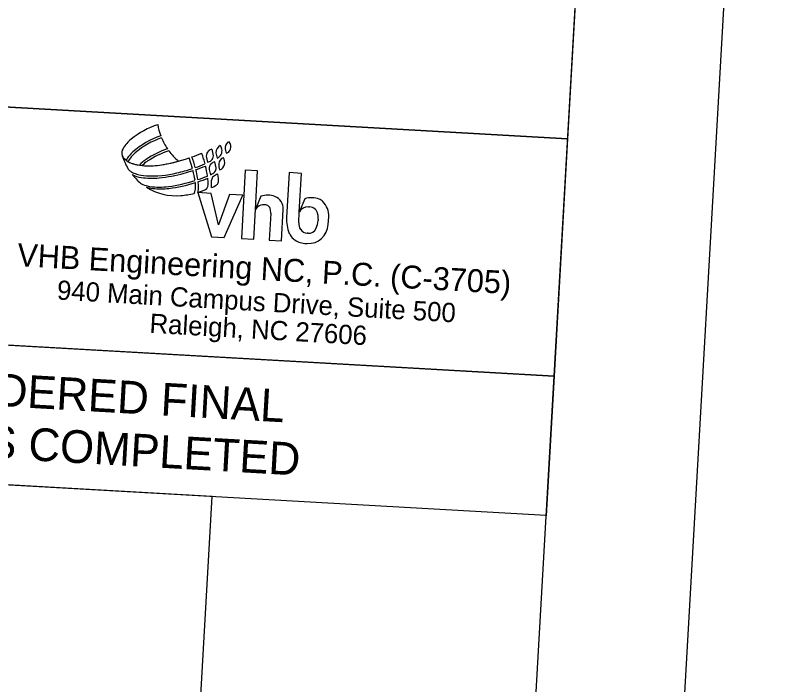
# Model space of a CAD drawing. Extents: x 2602909 to 2604669, y 617940 to 619640.
# Drawn here: x 2604541.7 to 2604668.9, y 618785.4 to 618898.1 of the extents above; entities that cross this region are included whole.
import ezdxf

# ---------------------------------------------------------------- set-up
doc = ezdxf.new("R2010")
doc.units = 0
for name, color, linetype in [('Default', 7, 'Continuous'), ('Scratch_Level_1', 7, 'Continuous'), ('Sheet Plan And Profile CELL', 7, 'Continuous'), ('Stewart Plot Border Xerox6279 and LJ5000', 7, 'Continuous')]:
    doc.layers.add(name, color=color, linetype=linetype)

msp = doc.modelspace()

# ---------------------------------------------------------------- linework, layer by layer
at = {"layer": 'Default'}
for p, q in [((2604575.1, 618874.39), (2604574.86, 618875.51)), ((2604571.55, 618872.28), (2604571.01, 618874.06)), ((2604573.89, 618874.35), (2604574.11, 618873.35)), ((2604575.54, 618872.4), (2604575.32, 618873.38)), ((2604574.38, 618872.13), (2604574.58, 618871.23)), ((2604580.45, 618872), (2604579.79, 618860.49)), ((2604582.52, 618871.88), (2604580.45, 618872)), ((2604587.83, 618871.58), (2604587.4, 618864.03)), ((2604589.91, 618871.46), (2604587.83, 618871.58)), ((2604572.47, 618868.21), (2604573.55, 618868.62)), ((2604574.69, 618868.09), (2604572.47, 618868.21)), ((2604572.47, 618868.21), (2604574.79, 618860.78)), ((2604575.95, 618862.8), (2604574.69, 618868.09)), ((2604577.81, 618867.91), (2604575.95, 618862.8)), ((2604576.88, 618860.66), (2604580.02, 618867.78)), ((2604580.02, 618867.78), (2604577.81, 618867.91)), ((2604583.09, 618867.61), (2604582.15, 618865.35)), ((2604590.48, 618867.19), (2604589.54, 618864.93)), ((2604584.73, 618864.68), (2604584.47, 618860.23)), ((2604586.55, 618860.11), (2604586.85, 618865.39)), ((2604591.06, 618865.83), (2604591.25, 618865.82)), ((2604592.7, 618863.73), (2604592.69, 618863.51)), ((2604594.41, 618862.83), (2604594.48, 618864.14)), ((2604590.99, 618861.37), (2604590.86, 618861.38)), ((2604574.79, 618860.78), (2604576.88, 618860.66)), ((2604579.79, 618860.49), (2604581.87, 618860.37)), ((2604584.47, 618860.23), (2604586.55, 618860.11)), ((2604590.46, 618859.68), (2604590.86, 618859.66)), ((2604432.67, 618848.7), (2604632.38, 618837.33)), ((2604432.67, 618848.7), (2604632.38, 618837.33)), ((2604632.38, 618837.32), (2604631.04, 618813.85)), ((2604632.38, 618837.32), (2604631.04, 618813.85)), ((2604631.04, 618813.87), (2604431.33, 618825.24)), ((2604631.04, 618813.87), (2604431.33, 618825.24))]:
    msp.add_line(p, q, dxfattribs=at)
msp.add_lwpolyline([(2604534.82, 618882.95), (2604634.66, 618877.26), (2604632.38, 618837.33), (2604532.54, 618843.01)], close=True, dxfattribs=at)
for points in [[(2604581.87, 618860.37), (2604582.15, 618865.35), (2604582.52, 618871.88)], [(2604589.44, 618863.16), (2604589.54, 618864.93), (2604589.91, 618871.46)]]:
    msp.add_lwpolyline(points, dxfattribs=at)
for centre, major_axis, start_param, end_param in [((2604570.26, 618866.03), (14.34, -0.82), 1.950459, 2.306295), ((2604576.13, 618881.51), (10.56, -0.6), 3.374816, 3.559712), ((2604570.73, 618864.53), (13.96, -0.79), 1.955908, 2.345415), ((2604570.73, 618864.53), (13.6, -0.77), 1.954608, 2.331375), ((2604576.13, 618881.51), (10.56, -0.6), 3.593328, 3.791245), ((2604564.9, 618872.68), (5.81, -0.33), 2.306295, 2.663056), ((2604576.8, 618875), (1.28, -0.07), 2.069357, 3.26373), ((2604574.09, 618874.93), (2.49, -0.14), 0.300085, 0.573578), ((2604578.06, 618875.84), (0.981, -0.056), 1.950799, 3.19085), ((2604576.66, 618875.96), (1.36, -0.08), 6.010502, 6.978239), ((2604561.2, 618874.88), (1.51, -0.09), 2.663056, 3.487291), ((2604565.02, 618871.08), (5.28, -0.3), 2.345415, 2.685879), ((2604565.1, 618871.18), (4.9, -0.28), 2.331375, 2.717794), ((2604572.24, 618861.29), (15.09, -0.86), 1.956929, 2.223843), ((2604572.24, 618861.29), (14.71, -0.84), 1.949325, 2.223843), ((2604576.13, 618881.51), (10.56, -0.6), 3.829221, 4.05458), ((2604561.38, 618902.71), (30.18, -1.72), 5.110242, 5.168312), ((2604535.65, 618862.24), (39.48, -2.25), 0.355324, 0.381952), ((2604574.91, 618874.45), (1.02, -0.06), 2.340862, 3.293303), ((2604575.08, 618874.25), (1.28, -0.07), 1.805558, 2.340862), ((2604578.01, 618875.08), (2.49, -0.14), 3.26373, 3.631752), ((2604575.26, 618875.22), (1.28, -0.07), 5.158115, 6.583255), ((2604579.57, 618875.82), (2.49, -0.14), 3.190836, 3.597778), ((2604576.94, 618875.86), (1.06, -0.06), 5.088672, 6.010509), ((2604568.81, 618877.14), (9.43, -0.54), 3.487291, 3.49224), ((2604560.49, 618874.62), (0.755, -0.043), 3.492238, 3.942132), ((2604560.49, 618874.62), (0.755, -0.043), 3.492238, 3.942132), ((2604568.81, 618877.14), (9.43, -0.54), 3.492238, 3.737263), ((2604562.66, 618876.62), (3.7, -0.21), 3.942115, 4.117328), ((2604562.66, 618876.62), (3.7, -0.21), 3.942115, 4.535322), ((2604567.57, 618868.17), (6.79, -0.39), 2.223843, 2.440018), ((2604561.38, 618902.71), (30.18, -1.72), 4.923489, 5.093727), ((2604535.65, 618862.24), (37.73, -2.15), 0.330018, 0.379866), ((2604554.82, 618868.13), (19.46, -1.11), 0.312292, 0.355324), ((2604573.92, 618874.62), (1.28, -0.07), 4.922279, 5.445148), ((2604574.08, 618874.42), (1.02, -0.06), 5.445151, 6.311085), ((2604577.2, 618872.96), (1.21, -0.07), 1.982585, 3.114577), ((2604575.41, 618873.29), (1.58, -0.09), 6.124862, 6.873863), ((2604561.99, 618873.07), (1.51, -0.09), 3.737263, 4.155114), ((2604562.66, 618876.62), (3.7, -0.21), 4.225969, 4.535322), ((2604564.34, 618883.67), (10.94, -0.62), 4.535322, 4.613027), ((2604564.34, 618883.67), (10.94, -0.62), 4.535322, 4.657076), ((2604567.57, 618868.17), (6.41, -0.36), 2.223843, 2.396036), ((2604564.34, 618883.67), (10.94, -0.62), 4.657076, 4.923489), ((2604564.34, 618883.67), (10.94, -0.62), 4.657076, 4.923489), ((2604561.38, 618902.71), (30.18, -1.72), 4.923489, 5.030725), ((2604561.38, 618902.71), (32.04, -1.83), 5.007435, 5.091777), ((2604561.38, 618902.71), (32.06, -1.83), 5.107726, 5.162272), ((2604561.38, 618902.71), (32.42, -1.85), 5.106941, 5.160619), ((2604554.82, 618868.13), (19.46, -1.11), 0.205325, 0.293478), ((2604575.34, 618872.33), (0.981, -0.056), 2.294387, 3.400315), ((2604575.62, 618871.97), (1.43, -0.08), 1.838184, 2.294391), ((2604574.56, 618872.33), (0.981, -0.056), 5.669754, 6.410867), ((2604578.1, 618872.89), (2.11, -0.12), 3.114567, 3.617561), ((2604575.71, 618873.23), (1.28, -0.07), 5.137017, 6.124854), ((2604562.95, 618874.43), (3.17, -0.18), 4.155114, 4.433304), ((2604563.6, 618875.4), (4.68, -0.27), 4.281835, 4.626581), ((2604568.81, 618877.14), (9.43, -0.54), 3.869789, 4.084312), ((2604564.2, 618877.99), (6.94, -0.4), 4.433304, 4.717272), ((2604564.76, 618888.78), (17.73, -1.01), 4.717272, 5.007435), ((2604563.61, 618894.76), (24.14, -1.38), 4.866042, 5.043468), ((2604561.38, 618902.71), (32.39, -1.84), 5.043468, 5.091439), ((2604561.51, 618868.92), (10.56, -0.6), 0.186675, 0.34709), ((2604535.65, 618862.24), (37.73, -2.15), 0.309699, 0.320394), ((2604561.51, 618868.92), (11.06, -0.63), 0.192744, 0.309699), ((2604561.38, 618902.71), (34.1, -1.94), 5.100586, 5.150688), ((2604574.2, 618872.61), (1.43, -0.08), 5.034707, 5.66976), ((2604576.39, 618869.28), (2.11, -0.12), 1.905419, 2.288613), ((2604572.25, 618870.31), (3.7, -0.21), 6.258511, 6.615609), ((2604563.78, 618870.99), (1.51, -0.09), 4.084312, 4.375641), ((2604564.73, 618883.26), (12.6, -0.72), 4.626581, 4.866042), ((2604564.68, 618891.74), (22.64, -1.29), 4.896065, 5.098239), ((2604565.27, 618889.97), (21.13, -1.2), 4.878361, 5.095384), ((2604561.51, 618868.92), (10.56, -0.6), 0.080866, 0.152313), ((2604561.38, 618902.71), (34.47, -1.96), 5.098273, 5.148033), ((2604561.51, 618868.92), (11.06, -0.63), 0.08898, 0.158557), ((2604554.82, 618868.13), (19.46, -1.11), 0.162521, 0.185756), ((2604571.19, 618869.87), (3.02, -0.17), 6.17953, 6.445706), ((2604568.52, 618869.84), (6.26, -0.36), 6.218327, 6.411973), ((2604575.61, 618870.3), (0.83, -0.047), 2.288613, 3.208516), ((2604575.13, 618870.18), (0.83, -0.047), 5.49053, 6.137671), ((2604565.09, 618874.13), (4.9, -0.28), 4.375641, 4.631331), ((2604565.59, 618875.84), (6.94, -0.4), 4.511808, 4.670453), ((2604568.81, 618877.14), (9.43, -0.54), 4.213149, 4.853258), ((2604566.05, 618881.02), (11.85, -0.67), 4.631331, 4.896065), ((2604566.17, 618881.7), (12.83, -0.73), 4.670453, 4.878361), ((2604569.82, 618869.11), (2.26, -0.13), 5.862276, 6.364042), ((2604568.81, 618869.15), (3.77, -0.21), 6.089473, 6.37216), ((2604573.21, 618869.54), (0.981, -0.056), 5.129856, 6.17953), ((2604574.28, 618871.14), (2.11, -0.12), 4.991009, 5.49053), ((2604568.23, 618883.92), (16.22, -0.92), 4.853258, 4.99278), ((2604584.2, 618864.27), (3.51, -0.2), 1.271815, 1.948427), ((2604584.66, 618865.51), (2.19, -0.12), 6.283185, 7.555001), ((2604591.58, 618863.85), (3.51, -0.2), 1.243417, 1.948427), ((2604583.55, 618864.6), (-1.58, 0.09), 4.330931, 5.84316), ((2604583.9, 618865.35), (-0.755, 0.043), 3.478495, 4.330931), ((2604592.22, 618865.43), (1.81, -0.1), 0.841181, 1.243417), ((2604591.12, 618864.33), (3.36, -0.19), 0, 0.841181), ((2604582.08, 618864.83), (2.64, -0.15), 0, 0.336903), ((2604590.97, 618864.25), (1.58, -0.09), 1.570796, 2.75299), ((2604591.17, 618864.31), (1.51, -0.09), 0.218399, 1.570796), ((2604593.44, 618863.69), (-6.04, 0.34), 0, 0.452165), ((2604588.92, 618863.72), (3.77, -0.21), 5.93764, 6.283185), ((2604588.93, 618863.95), (3.77, -0.21), 6.283185, 6.501584), ((2604591.32, 618863.05), (-1.89, 0.11), 6.283185, 6.906012), ((2604591.05, 618863.02), (3.36, -0.19), 4.712389, 6.283185), ((2604591.07, 618862.8), (1.43, -0.08), 4.712389, 5.93764), ((2604590.09, 618862.29), (-2.41, 0.14), 0.452165, 0.946963), ((2604590.94, 618862.81), (-1.43, 0.08), 0.622827, 1.570796), ((2604590.64, 618862.97), (-3.29, 0.19), 0.946963, 1.570796)]:
    msp.add_ellipse(centre, major_axis=major_axis, ratio=0.999914, start_param=start_param, end_param=end_param, dxfattribs=at)
at = {"layer": 'Scratch_Level_1'}
msp.add_lwpolyline([(2604574.88, 618817.07), (2604431.33, 618825.24), (2604442.75, 619025.97), (2603144.9, 619099.88), (2603085.2, 618051.58), (2604526.6, 617969.49)], close=True, dxfattribs=at)
msp.add_lwpolyline([(2604574.88, 618817.07), (2604431.33, 618825.24), (2604442.75, 619025.97), (2603144.9, 619099.88), (2603085.2, 618051.58), (2604526.6, 617969.49)], close=True, dxfattribs=at)
at = {"layer": 'Sheet Plan And Profile CELL'}
msp.add_line((2604432.67, 618848.7), (2604632.38, 618837.33), dxfattribs=at)
for points in [[(2604642.48, 619014.59), (2603144.9, 619099.88), (2603085.2, 618051.58), (2604582.77, 617966.29)], [(2604541.21, 618995.27), (2604641.04, 618989.59), (2604634.66, 618877.26), (2604534.82, 618882.94)]]:
    msp.add_lwpolyline(points, close=True, dxfattribs=at)
at = {"layer": 'Stewart Plot Border Xerox6279 and LJ5000'}
msp.add_lwpolyline([(2602909.06, 618036.57), (2604606.31, 617939.91), (2604668.86, 619038.13), (2602971.61, 619134.8)], close=True, dxfattribs=at)

# ---------------------------------------------------------------- texts
at = {"layer": 'Default'}
for s, height, rotation, p in [('VHB Engineering NC, P.C. (C-3705)', 3.8596, 356.7403, (2604542.01, 618855.86)), ('940 Main Campus Drive, Suite 500', 3.2388, 356.7015, (2604548.71, 618850.23)), ('Raleigh, NC 27606', 3.2388, 356.7015, (2604564.28, 618844.64)), ('DOCUMENT NOT CONSIDERED FINAL', 5.5, 356.7403, (2604453.12, 618837.18)), ('DOCUMENT NOT CONSIDERED FINAL', 5.5, 356.7403, (2604453.12, 618837.18)), ('UNLESS ALL SIGNATURES COMPLETED', 5.5, 356.7403, (2604447.55, 618828.68)), ('UNLESS ALL SIGNATURES COMPLETED', 5.5, 356.7403, (2604447.55, 618828.68))]:
    msp.add_text(s, height=height, rotation=rotation, dxfattribs=at).set_placement(p)

doc.saveas('drawing.dxf')
